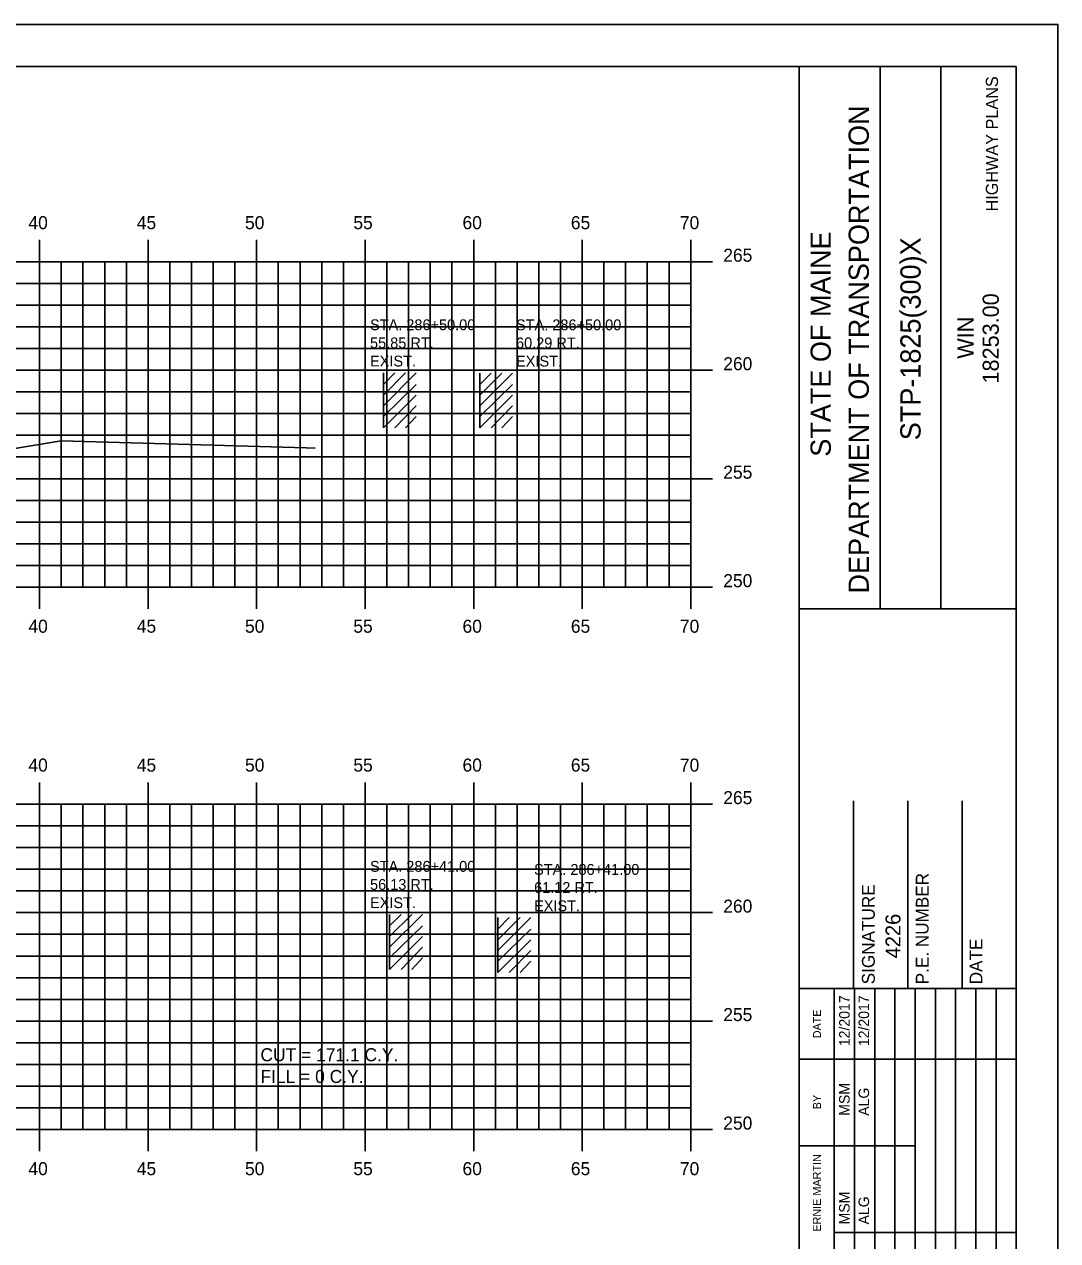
# Model space of a CAD drawing. Extents: x 856903 to 857073, y 366268 to 366378.
# Drawn here: x 857025.1 to 857072.7, y 366322.1 to 366378.2 of the extents above; entities that cross this region are included whole.
import ezdxf

# ---------------------------------------------------------------- set-up
doc = ezdxf.new("R2010")
doc.units = 0
for name, color, linetype in [('ANNOTATION', 7, 'Continuous'), ('BORDER', 7, 'Continuous'), ('D_Text_Monospaced', 7, 'Continuous'), ('H_V ANNOTATION', 7, 'Continuous'), ('HIGHWAY_TITLE', 7, 'Continuous'), ('MAJOR', 7, 'Continuous'), ('MINOR', 7, 'Continuous'), ('PLOT BOUNDARY', 7, 'Continuous'), ('S_Buildings', 7, 'Continuous'), ('S_Roadway_Centerline', 7, 'Continuous')]:
    doc.layers.add(name, color=color, linetype=linetype)

msp = doc.modelspace()

# ---------------------------------------------------------------- linework, layer by layer
at = {"layer": 'BORDER'}
for p, q in [((857070.784, 366376.236), (856910.784, 366376.236)), ((857060.784, 366271.236), (857060.784, 366376.239)), ((857064.513, 366351.234), (857064.513, 366376.234)), ((857067.308, 366351.234), (857067.308, 366376.234)), ((857070.784, 366271.236), (857070.784, 366376.236)), ((857060.785, 366351.231), (857070.784, 366351.231)), ((857063.284, 366333.739), (857063.284, 366342.387)), ((857065.784, 366333.739), (857065.784, 366342.387)), ((857068.284, 366333.739), (857068.284, 366342.387)), ((857060.784, 366333.739), (857070.784, 366333.739))]:
    msp.add_line(p, q, dxfattribs=at)
for points in [[(857062.399, 366330.489), (857062.399, 366333.739)], [(857063.332, 366316.242), (857063.332, 366333.739)], [(857064.263, 366333.739), (857064.263, 366316.242)], [(857065.195, 366316.242), (857065.195, 366333.739)], [(857066.127, 366316.242), (857066.127, 366333.739)], [(857067.058, 366316.242), (857067.058, 366333.739)], [(857067.99, 366316.242), (857067.99, 366333.739)], [(857068.922, 366316.242), (857068.922, 366333.739)], [(857069.853, 366316.242), (857069.853, 366333.739)], [(857062.4, 366316.242), (857062.4, 366333.033)], [(857060.784, 366330.489), (857070.784, 366330.489)], [(857060.784, 366326.489), (857062.4, 366326.489)], [(857062.399, 366326.489), (857066.126, 366326.489)], [(857062.399, 366322.489), (857070.784, 366322.489)]]:
    msp.add_lwpolyline(points, dxfattribs=at)
at = {"layer": 'MAJOR'}
for p, q in [((857025.784, 366368.238), (857025.784, 366367.236)), ((857030.784, 366368.238), (857030.784, 366367.236)), ((857035.784, 366368.238), (857035.784, 366367.236)), ((857040.784, 366368.238), (857040.784, 366367.236)), ((857045.784, 366368.238), (857045.784, 366367.236)), ((857050.784, 366368.238), (857050.784, 366367.236)), ((857055.784, 366368.238), (857055.784, 366367.236)), ((856915.784, 366367.236), (857055.784, 366367.236)), ((856915.784, 366367.236), (857055.784, 366367.236)), ((857025.784, 366352.236), (857025.784, 366367.236)), ((857030.784, 366352.236), (857030.784, 366367.236)), ((857035.784, 366352.236), (857035.784, 366367.236)), ((857040.784, 366352.236), (857040.784, 366367.236)), ((857045.784, 366352.236), (857045.784, 366367.236)), ((857050.784, 366352.236), (857050.784, 366367.236)), ((857056.786, 366367.236), (857054.782, 366367.236)), ((857055.784, 366352.236), (857055.784, 366367.236)), ((857055.784, 366352.236), (857055.784, 366367.236)), ((856915.784, 366362.236), (857055.784, 366362.236)), ((857056.786, 366362.236), (857054.782, 366362.236)), ((856915.784, 366357.236), (857055.784, 366357.236)), ((857056.786, 366357.236), (857054.782, 366357.236)), ((856915.784, 366352.236), (857055.784, 366352.236)), ((856915.784, 366352.236), (857055.784, 366352.236)), ((857025.784, 366351.234), (857025.784, 366352.236)), ((857030.784, 366351.234), (857030.784, 366352.236)), ((857035.784, 366351.234), (857035.784, 366352.236)), ((857040.784, 366351.234), (857040.784, 366352.236)), ((857045.784, 366351.234), (857045.784, 366352.236)), ((857050.784, 366351.234), (857050.784, 366352.236)), ((857056.786, 366352.236), (857054.782, 366352.236)), ((857055.784, 366351.234), (857055.784, 366352.236)), ((857025.784, 366343.238), (857025.784, 366342.236)), ((857030.784, 366343.238), (857030.784, 366342.236)), ((857035.784, 366343.238), (857035.784, 366342.236)), ((857040.784, 366343.238), (857040.784, 366342.236)), ((857045.784, 366343.238), (857045.784, 366342.236)), ((857050.784, 366343.238), (857050.784, 366342.236)), ((857055.784, 366343.238), (857055.784, 366342.236)), ((856915.784, 366342.236), (857055.784, 366342.236)), ((856915.784, 366342.236), (857055.784, 366342.236)), ((857025.784, 366327.236), (857025.784, 366342.236)), ((857030.784, 366327.236), (857030.784, 366342.236)), ((857035.784, 366327.236), (857035.784, 366342.236)), ((857040.784, 366327.236), (857040.784, 366342.236)), ((857045.784, 366327.236), (857045.784, 366342.236)), ((857050.784, 366327.236), (857050.784, 366342.236)), ((857056.786, 366342.236), (857054.782, 366342.236)), ((857055.784, 366327.236), (857055.784, 366342.236)), ((857055.784, 366327.236), (857055.784, 366342.236)), ((856915.784, 366337.236), (857055.784, 366337.236)), ((857056.786, 366337.236), (857054.782, 366337.236)), ((856915.784, 366332.236), (857055.784, 366332.236)), ((857056.786, 366332.236), (857054.782, 366332.236)), ((856915.784, 366327.236), (857055.784, 366327.236)), ((856915.784, 366327.236), (857055.784, 366327.236)), ((857025.784, 366326.234), (857025.784, 366327.236)), ((857030.784, 366326.234), (857030.784, 366327.236)), ((857035.784, 366326.234), (857035.784, 366327.236)), ((857040.784, 366326.234), (857040.784, 366327.236)), ((857045.784, 366326.234), (857045.784, 366327.236)), ((857050.784, 366326.234), (857050.784, 366327.236)), ((857056.786, 366327.236), (857054.782, 366327.236)), ((857055.784, 366326.234), (857055.784, 366327.236))]:
    msp.add_line(p, q, dxfattribs=at)
at = {"layer": 'MINOR'}
for p, q in [((857026.784, 366352.236), (857026.784, 366367.236)), ((857027.784, 366352.236), (857027.784, 366367.236)), ((857028.784, 366352.236), (857028.784, 366367.236)), ((857029.784, 366352.236), (857029.784, 366367.236)), ((857031.784, 366352.236), (857031.784, 366367.236)), ((857032.784, 366352.236), (857032.784, 366367.236)), ((857033.784, 366352.236), (857033.784, 366367.236)), ((857034.784, 366352.236), (857034.784, 366367.236)), ((857036.784, 366352.236), (857036.784, 366367.236)), ((857037.784, 366352.236), (857037.784, 366367.236)), ((857038.784, 366352.236), (857038.784, 366367.236)), ((857039.784, 366352.236), (857039.784, 366367.236)), ((857041.784, 366352.236), (857041.784, 366367.236)), ((857042.784, 366352.236), (857042.784, 366367.236)), ((857043.784, 366352.236), (857043.784, 366367.236)), ((857044.784, 366352.236), (857044.784, 366367.236)), ((857046.784, 366352.236), (857046.784, 366367.236)), ((857047.784, 366352.236), (857047.784, 366367.236)), ((857048.784, 366352.236), (857048.784, 366367.236)), ((857049.784, 366352.236), (857049.784, 366367.236)), ((857051.784, 366352.236), (857051.784, 366367.236)), ((857052.784, 366352.236), (857052.784, 366367.236)), ((857053.784, 366352.236), (857053.784, 366367.236)), ((857054.784, 366352.236), (857054.784, 366367.236)), ((856915.784, 366366.236), (857055.784, 366366.236)), ((857055.784, 366366.236), (857054.782, 366366.236)), ((856915.784, 366365.236), (857055.784, 366365.236)), ((857055.784, 366365.236), (857054.782, 366365.236)), ((856915.784, 366364.236), (857055.784, 366364.236)), ((857055.784, 366364.236), (857054.782, 366364.236)), ((856915.784, 366363.236), (857055.784, 366363.236)), ((857055.784, 366363.236), (857054.782, 366363.236)), ((856915.784, 366361.236), (857055.784, 366361.236)), ((857055.784, 366361.236), (857054.782, 366361.236)), ((856915.784, 366360.236), (857055.784, 366360.236)), ((857055.784, 366360.236), (857054.782, 366360.236)), ((856915.784, 366359.236), (857055.784, 366359.236)), ((857055.784, 366359.236), (857054.782, 366359.236)), ((856915.784, 366358.236), (857055.784, 366358.236)), ((857055.784, 366358.236), (857054.782, 366358.236)), ((856915.784, 366356.236), (857055.784, 366356.236)), ((857055.784, 366356.236), (857054.782, 366356.236)), ((856915.784, 366355.236), (857055.784, 366355.236)), ((857055.784, 366355.236), (857054.782, 366355.236)), ((856915.784, 366354.236), (857055.784, 366354.236)), ((857055.784, 366354.236), (857054.782, 366354.236)), ((856915.784, 366353.236), (857055.784, 366353.236)), ((857055.784, 366353.236), (857054.782, 366353.236)), ((857026.784, 366327.236), (857026.784, 366342.236)), ((857027.784, 366327.236), (857027.784, 366342.236)), ((857028.784, 366327.236), (857028.784, 366342.236)), ((857029.784, 366327.236), (857029.784, 366342.236)), ((857031.784, 366327.236), (857031.784, 366342.236)), ((857032.784, 366327.236), (857032.784, 366342.236)), ((857033.784, 366327.236), (857033.784, 366342.236)), ((857034.784, 366327.236), (857034.784, 366342.236)), ((857036.784, 366327.236), (857036.784, 366342.236)), ((857037.784, 366327.236), (857037.784, 366342.236)), ((857038.784, 366327.236), (857038.784, 366342.236)), ((857039.784, 366327.236), (857039.784, 366342.236)), ((857041.784, 366327.236), (857041.784, 366342.236)), ((857042.784, 366327.236), (857042.784, 366342.236)), ((857043.784, 366327.236), (857043.784, 366342.236)), ((857044.784, 366327.236), (857044.784, 366342.236)), ((857046.784, 366327.236), (857046.784, 366342.236)), ((857047.784, 366327.236), (857047.784, 366342.236)), ((857048.784, 366327.236), (857048.784, 366342.236)), ((857049.784, 366327.236), (857049.784, 366342.236)), ((857051.784, 366327.236), (857051.784, 366342.236)), ((857052.784, 366327.236), (857052.784, 366342.236)), ((857053.784, 366327.236), (857053.784, 366342.236)), ((857054.784, 366327.236), (857054.784, 366342.236)), ((856915.784, 366341.236), (857055.784, 366341.236)), ((857055.784, 366341.236), (857054.782, 366341.236)), ((856915.784, 366340.236), (857055.784, 366340.236)), ((857055.784, 366340.236), (857054.782, 366340.236)), ((856915.784, 366339.236), (857055.784, 366339.236)), ((857055.784, 366339.236), (857054.782, 366339.236)), ((856915.784, 366338.236), (857055.784, 366338.236)), ((857055.784, 366338.236), (857054.782, 366338.236)), ((856915.784, 366336.236), (857055.784, 366336.236)), ((857055.784, 366336.236), (857054.782, 366336.236)), ((856915.784, 366335.236), (857055.784, 366335.236)), ((857055.784, 366335.236), (857054.782, 366335.236)), ((856915.784, 366334.236), (857055.784, 366334.236)), ((857055.784, 366334.236), (857054.782, 366334.236)), ((856915.784, 366333.236), (857055.784, 366333.236)), ((857055.784, 366333.236), (857054.782, 366333.236)), ((856915.784, 366331.236), (857055.784, 366331.236)), ((857055.784, 366331.236), (857054.782, 366331.236)), ((856915.784, 366330.236), (857055.784, 366330.236)), ((857055.784, 366330.236), (857054.782, 366330.236)), ((856915.784, 366329.236), (857055.784, 366329.236)), ((857055.784, 366329.236), (857054.782, 366329.236)), ((856915.784, 366328.236), (857055.784, 366328.236)), ((857055.784, 366328.236), (857054.782, 366328.236))]:
    msp.add_line(p, q, dxfattribs=at)
at = {"layer": 'PLOT BOUNDARY'}
msp.add_lwpolyline([(856902.691, 366268.177), (857072.691, 366268.177), (857072.691, 366378.177), (856902.691, 366378.177)], close=True, dxfattribs=at)
at = {"layer": 'S_Buildings'}
for p, q in [((857041.633, 366359.583), (857041.633, 366362.109)), ((857041.633, 366360.6), (857043.142, 366362.109)), ((857041.633, 366361.092), (857042.65, 366362.109)), ((857041.633, 366361.584), (857042.158, 366362.109)), ((857046.07, 366359.579), (857046.07, 366362.105)), ((857046.07, 366360.596), (857047.579, 366362.105)), ((857046.07, 366361.088), (857047.087, 366362.105)), ((857046.07, 366361.58), (857046.595, 366362.105)), ((857041.633, 366360.108), (857043.142, 366361.584)), ((857046.07, 366360.103), (857047.579, 366361.58)), ((857041.633, 366359.583), (857043.142, 366361.092)), ((857046.07, 366359.579), (857047.579, 366361.088)), ((857042.158, 366359.583), (857043.142, 366360.6)), ((857046.595, 366359.579), (857047.579, 366360.596)), ((857042.65, 366359.583), (857043.142, 366360.108)), ((857047.087, 366359.579), (857047.579, 366360.103)), ((857041.911, 366334.62), (857041.911, 366337.146)), ((857041.911, 366335.637), (857043.421, 366337.146)), ((857041.911, 366336.129), (857042.928, 366337.146)), ((857041.911, 366336.621), (857042.436, 366337.146)), ((857046.902, 366334.478), (857046.902, 366337.005)), ((857046.902, 366335.495), (857048.411, 366337.005)), ((857046.902, 366335.988), (857047.919, 366337.005)), ((857046.902, 366336.48), (857047.427, 366337.005)), ((857041.911, 366335.145), (857043.421, 366336.621)), ((857046.902, 366335.003), (857048.411, 366336.48)), ((857041.911, 366334.62), (857043.421, 366336.129)), ((857046.902, 366334.478), (857048.411, 366335.988)), ((857042.436, 366334.62), (857043.421, 366335.637)), ((857042.928, 366334.62), (857043.421, 366335.145)), ((857047.427, 366334.478), (857048.411, 366335.495)), ((857047.919, 366334.478), (857048.411, 366335.003))]:
    msp.add_line(p, q, dxfattribs=at)
at = {"layer": 'S_Roadway_Centerline'}
msp.add_lwpolyline([(856967.936, 366359.549), (856970.642, 366359.617), (856975.724, 366359.876), (856979.041, 366359.911), (856985.813, 366360.02), (856990.425, 366359.892), (856996.778, 366359.594), (856999.213, 366359.549), (857002.296, 366359.438), (857002.712, 366359.895), (857002.85, 366360.035), (857003.549, 366359.959), (857004.447, 366359.863), (857007.994, 366359.391), (857009.968, 366359.305), (857021.509, 366358.935), (857024.373, 366358.587), (857026.776, 366358.981), (857038.061, 366358.662), (857038.485, 366358.646)], dxfattribs=at)

# ---------------------------------------------------------------- texts
at = {"layer": 'ANNOTATION'}
msp.add_text('4226', height=0.69, rotation=90, dxfattribs=at).set_placement((857065.449, 366335.13))
for s, p in [('CUT = 171.1 C.Y.', (857035.96, 366330.386)), ('FILL = 0 C.Y.', (857035.96, 366329.384))]:
    msp.add_text(s, height=0.6, dxfattribs=at).set_placement(p)
at = {"layer": 'BORDER'}
for s, height, p in [('DEPARTMENT OF TRANSPORTATION', 0.93176, (857063.991, 366351.942)), ('STATE OF MAINE', 0.93176, (857062.239, 366358.248)), ('STP-1825(300)X', 0.93176, (857066.376, 366359.008)), ('18253.00', 0.7453, (857069.98, 366361.623)), ('WIN', 0.7453, (857068.821, 366362.766)), ('P.E. NUMBER', 0.59055, (857066.745, 366333.932)), ('SIGNATURE', 0.5906, (857064.265, 366333.932)), ('DATE', 0.5906, (857069.225, 366333.932)), ('12/2017', 0.4845, (857063.107, 366331.081)), ('12/2017', 0.4845, (857064.002, 366331.081)), ('DATE', 0.3714, (857061.788, 366331.445)), ('MSM', 0.4845, (857063.107, 366327.872)), ('ALG', 0.4845, (857064.002, 366327.872)), ('BY', 0.3714, (857061.788, 366328.174)), ('ERNIE MARTIN', 0.37275, (857061.788, 366322.531)), ('MSM', 0.4845, (857063.107, 366322.863)), ('ALG', 0.4845, (857064.002, 366322.863))]:
    msp.add_text(s, height=height, rotation=90, dxfattribs=at).set_placement(p)
at = {"layer": 'D_Text_Monospaced'}
for s, height, p in [('STA. 286+50.00', 0.49998, (857041.009, 366364.081)), ('STA. 286+50.00', 0.49998, (857047.736, 366364.077)), ('55.85 RT.', 0.5, (857041.009, 366363.247)), ('60.29 RT.', 0.5, (857047.736, 366363.243)), ('EXIST. ', 0.5, (857041.009, 366362.407)), ('EXIST. ', 0.5, (857047.736, 366362.403)), ('STA. 286+41.00', 0.49998, (857041.009, 366339.118)), ('STA. 286+41.00', 0.49998, (857048.568, 366338.977)), ('56.13 RT.', 0.5, (857041.009, 366338.284)), ('61.12 RT.', 0.5, (857048.568, 366338.143)), ('EXIST. ', 0.5, (857041.009, 366337.444)), ('EXIST. ', 0.5, (857048.568, 366337.303))]:
    msp.add_text(s, height=height, dxfattribs=at).set_placement(p)
at = {"layer": 'H_V ANNOTATION'}
for s, p in [('40', (857025.27, 366368.736)), ('45', (857030.262, 366368.736)), ('50', (857035.249, 366368.736)), ('55', (857040.241, 366368.736)), ('60', (857045.27, 366368.736)), ('65', (857050.262, 366368.736)), ('70', (857055.286, 366368.736)), ('265', (857057.284, 366367.236)), ('260', (857057.284, 366362.236)), ('255', (857057.284, 366357.236)), ('250', (857057.284, 366352.236)), ('40', (857025.27, 366350.136)), ('45', (857030.262, 366350.136)), ('50', (857035.249, 366350.136)), ('55', (857040.241, 366350.136)), ('60', (857045.27, 366350.136)), ('65', (857050.262, 366350.136)), ('70', (857055.286, 366350.136)), ('40', (857025.27, 366343.736)), ('45', (857030.262, 366343.736)), ('50', (857035.249, 366343.736)), ('55', (857040.241, 366343.736)), ('60', (857045.27, 366343.736)), ('65', (857050.262, 366343.736)), ('70', (857055.286, 366343.736)), ('265', (857057.284, 366342.236)), ('260', (857057.284, 366337.236)), ('255', (857057.284, 366332.236)), ('250', (857057.284, 366327.236)), ('40', (857025.27, 366325.136)), ('45', (857030.262, 366325.136)), ('50', (857035.249, 366325.136)), ('55', (857040.241, 366325.136)), ('60', (857045.27, 366325.136)), ('65', (857050.262, 366325.136)), ('70', (857055.286, 366325.136))]:
    msp.add_text(s, height=0.6, dxfattribs=at).set_placement(p)
at = {"layer": 'HIGHWAY_TITLE'}
msp.add_text('HIGHWAY PLANS', height=0.55901, rotation=90, dxfattribs=at).set_placement((857069.942, 366369.552))

doc.saveas('drawing.dxf')
